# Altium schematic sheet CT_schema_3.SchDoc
size 313 x 200 mm
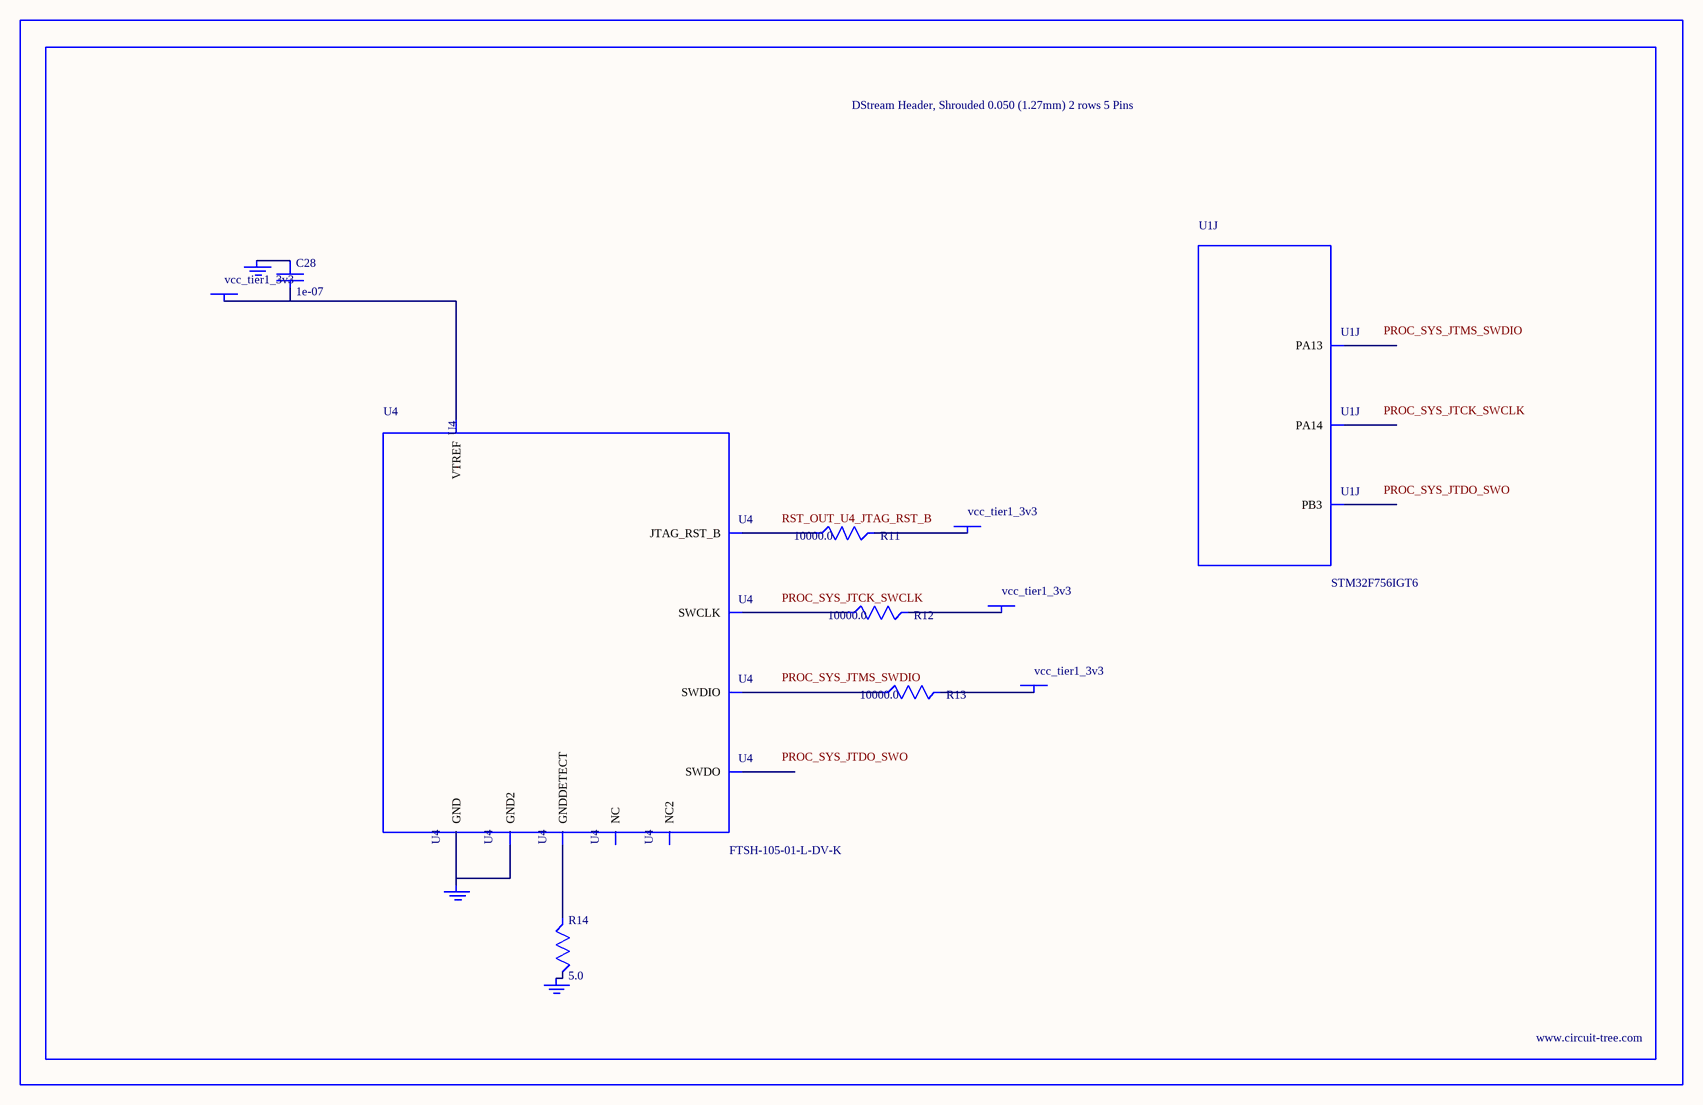
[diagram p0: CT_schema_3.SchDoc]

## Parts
BORDER2  (no value)
C28  1e-07  [C0402]
GND_INSTANCE_2_0  (no value)
GND_INSTANCE_2_1  (no value)
GND_INSTANCE_2_2  (no value)
POWER_INSTANCE_2_0  vcc_tier1_3v3
POWER_INSTANCE_2_1  vcc_tier1_3v3
POWER_INSTANCE_2_2  vcc_tier1_3v3
POWER_INSTANCE_2_3  vcc_tier1_3v3
R11  10000.0  [R0603]
R12  10000.0  [R0603]
R13  10000.0  [R0603]
R14  5.0  [R0603]
U1  STM32F756IGT6  [LQFP176]  (part J of 14)
U4  FTSH-105-01-L-DV-K  [SAMTEC_FTSH-105-01-L-DV-K]

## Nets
NetC28_1: C28.1 GND_INSTANCE_2_0.0(GND)
NetC28_2: C28.2 POWER_INSTANCE_2_0.0(PWR) U4.1(VTREF)
NetGND_INSTANCE_2_1_0: GND_INSTANCE_2_1.0(GND) R14.2
NetGND_INSTANCE_2_2_0: GND_INSTANCE_2_2.0(GND) U4.3(GND) U4.5(GND2)
NetPOWER_INSTANCE_2_1_0: POWER_INSTANCE_2_1.0(PWR) R13.2
NetPOWER_INSTANCE_2_2_0: POWER_INSTANCE_2_2.0(PWR) R12.2
NetPOWER_INSTANCE_2_3_0: POWER_INSTANCE_2_3.0(PWR) R11.2
NetR11_1: R11.1 U4.10(JTAG_RST_B)
NetR12_1: R12.1 U4.4(SWCLK)
NetR13_1: R13.1 U4.2(SWDIO)
NetR14_1: R14.1 U4.9(GNDDETECT)

Not connected (* = marked no-connect by the designer): U1 124(PA13) 137(PA14) 161(PB3); U4 6(SWDO) 7(NC) 8(NC2)

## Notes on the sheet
- Labels drawn without touching a wire or pin: PROC_SYS_JTCK_SWCLK, PROC_SYS_JTDO_SWO, PROC_SYS_JTMS_SWDIO, RST_OUT_U4_JTAG_RST_B

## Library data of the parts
BORDER2 = BORDER_PAGE2
C28 = C0402C104K3RACTU
GND_INSTANCE_2_0-GND_INSTANCE_2_2 = GND
POWER_INSTANCE_2_0-POWER_INSTANCE_2_3 = PWR
R11-R13 = RC0603JR-0710KL
R14 = ERJ-3GEYJ5R1V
